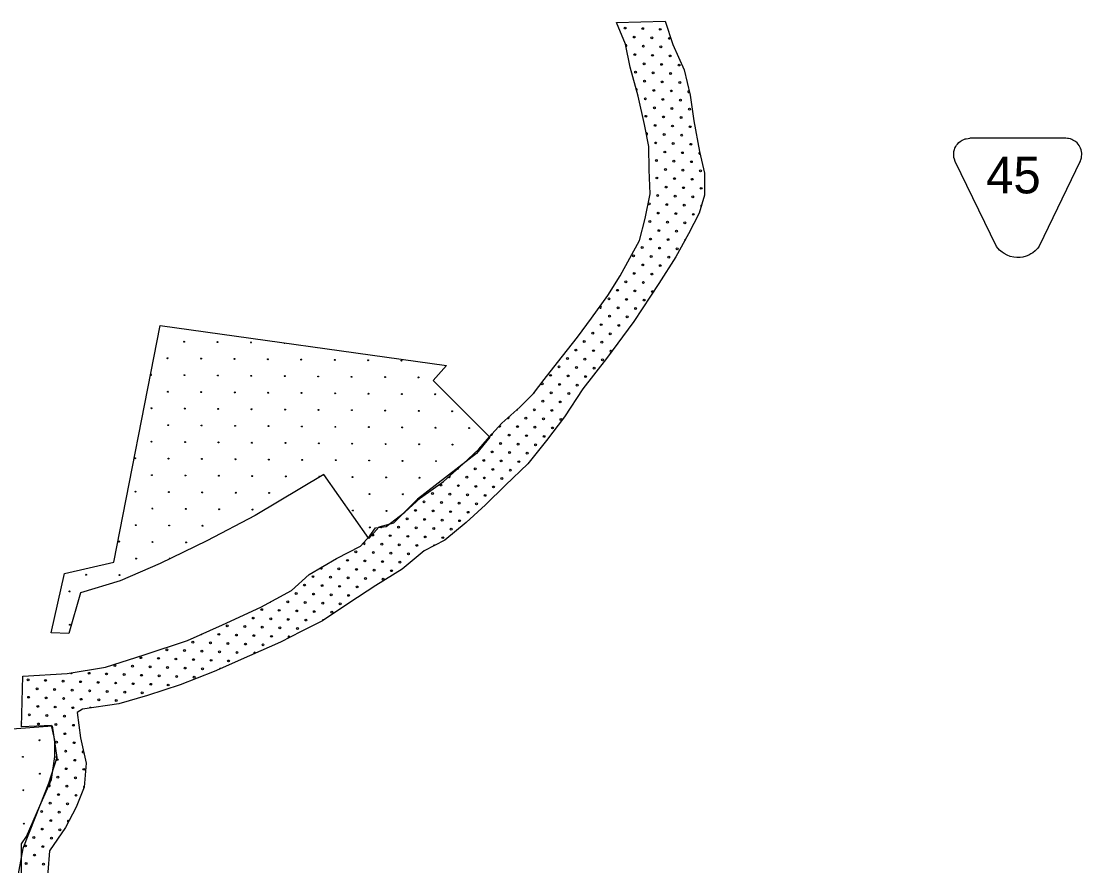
# Model space of a CAD drawing. Extents: x 1612280 to 1883141, y 560852 to 780851.
# Drawn here: x 1772365 to 1784565, y 675742 to 685456 of the extents above; entities that cross this region are included whole.
import ezdxf

# ---------------------------------------------------------------- set-up
doc = ezdxf.new("R2010")
doc.units = 0
for name, color, linetype in [('DESIGN - EROSION CONTROL - Devices', 7, 'Continuous'), ('DESIGN - ROW - Easement Linework and Patterning', 7, 'Continuous'), ('DESIGN - SCRATCH - User 1', 7, 'Continuous'), ('DESIGN - TRAFFIC CONTROL PERMANENT - Pavement Marking Text', 7, 'Continuous')]:
    doc.layers.add(name, color=color, linetype=linetype)

msp = doc.modelspace()

# ---------------------------------------------------------------- linework, layer by layer
at = {"layer": 'DESIGN - EROSION CONTROL - Devices'}
for centre in [(1774239, 681769), (1774239, 681769), (1774623, 681766), (1774623, 681766), (1775008, 681762), (1775008, 681762), (1774048, 681579), (1774048, 681579), (1774433, 681575), (1774433, 681575), (1774817, 681572), (1774817, 681572), (1775202, 681568), (1775202, 681568), (1775586, 681564), (1775586, 681564), (1775971, 681560), (1775971, 681560), (1776356, 681557), (1776356, 681557), (1776740, 681553), (1776740, 681553), (1774242, 681385), (1774242, 681385), (1774627, 681381), (1774627, 681381), (1775011, 681377), (1775011, 681377), (1775396, 681374), (1775396, 681374), (1775781, 681370), (1775781, 681370), (1776165, 681366), (1776165, 681366), (1776550, 681363), (1776550, 681363), (1776934, 681359), (1776934, 681359), (1774052, 681194), (1774052, 681194), (1774436, 681191), (1774436, 681191), (1774821, 681187), (1774821, 681187), (1775206, 681183), (1775206, 681183), (1775590, 681180), (1775590, 681180), (1775975, 681176), (1775975, 681176), (1776359, 681172), (1776359, 681172), (1776744, 681168), (1776744, 681168), (1777128, 681165), (1777128, 681165), (1773862, 681004), (1773862, 681004), (1774246, 681000), (1774246, 681000), (1774631, 680997), (1774631, 680997), (1775015, 680993), (1775015, 680993), (1775400, 680989), (1775400, 680989), (1775784, 680985), (1775784, 680985), (1776169, 680982), (1776169, 680982), (1776553, 680978), (1776553, 680978), (1776938, 680974), (1776938, 680974), (1777322, 680970), (1777322, 680970), (1774056, 680810), (1774056, 680810), (1774440, 680806), (1774440, 680806), (1774825, 680802), (1774825, 680802), (1775209, 680799), (1775209, 680799), (1775594, 680795), (1775594, 680795), (1775978, 680791), (1775978, 680791), (1776363, 680788), (1776363, 680788), (1776748, 680784), (1776748, 680784), (1777132, 680780), (1777132, 680780), (1777517, 680776), (1777517, 680776), (1773865, 680620), (1773865, 680620), (1774250, 680616), (1774250, 680616), (1774634, 680612), (1774634, 680612), (1775019, 680608), (1775019, 680608), (1775403, 680605), (1775403, 680605), (1775788, 680601), (1775788, 680601), (1776173, 680597), (1776173, 680597), (1776557, 680593), (1776557, 680593), (1776942, 680590), (1776942, 680590), (1777326, 680586), (1777326, 680586), (1773675, 680429), (1773675, 680429), (1774059, 680425), (1774059, 680425), (1774444, 680422), (1774444, 680422), (1774829, 680418), (1774829, 680418), (1775213, 680414), (1775213, 680414), (1775598, 680410), (1775598, 680410), (1775982, 680407), (1775982, 680407), (1776367, 680403), (1776367, 680403), (1776751, 680399), (1776751, 680399), (1777136, 680396), (1777136, 680396), (1773869, 680235), (1773869, 680235), (1774254, 680231), (1774254, 680231), (1774638, 680228), (1774638, 680228), (1775023, 680224), (1775023, 680224), (1775407, 680220), (1775407, 680220), (1776176, 680213), (1776176, 680213), (1776561, 680209), (1776561, 680209), (1776945, 680205), (1776945, 680205), (1773679, 680045), (1773679, 680045), (1774063, 680041), (1774063, 680041), (1774448, 680037), (1774448, 680037), (1774832, 680033), (1774832, 680033), (1775217, 680030), (1775217, 680030), (1776370, 680018), (1776370, 680018), (1776755, 680015), (1776755, 680015), (1773873, 679850), (1773873, 679850), (1774257, 679847), (1774257, 679847), (1774642, 679843), (1774642, 679843), (1775026, 679839), (1775026, 679839), (1776180, 679828), (1776180, 679828), (1776565, 679824), (1776565, 679824), (1773682, 679660), (1773682, 679660), (1774067, 679656), (1774067, 679656), (1774451, 679653), (1774451, 679653), (1776374, 679634), (1776374, 679634), (1773492, 679470), (1773492, 679470), (1773876, 679466), (1773876, 679466), (1774261, 679462), (1774261, 679462), (1773686, 679275), (1773686, 679275), (1773111, 679089), (1773111, 679089), (1773496, 679085), (1773496, 679085), (1772921, 678898), (1772921, 678898), (1772924, 678514), (1772924, 678514), (1772576, 677185), (1772576, 677185), (1772385, 676995), (1772385, 676995), (1772579, 676801), (1772579, 676801), (1772389, 676610), (1772389, 676610), (1772393, 676226), (1772393, 676226)]:
    msp.add_circle(centre, 5.28, dxfattribs=at)
for centre, start, end in [((1775392, 681758), 202.5952, 321.4914), ((1773858, 681389), 201.616, 136.1823), ((1775792, 680216), 336.6657, 265.4618), ((1774071, 679272), 10.465, 221.9957), ((1772770, 676991), 44.8233, 327.4361)]:
    msp.add_arc(centre, 5.28, start, end, dxfattribs=at)
at = {"layer": 'DESIGN - ROW - Easement Linework and Patterning'}
for points in [[(1783584, 682864), (1783109, 683844), (1783099, 683871), (1783094, 683889), (1783092, 683907), (1783091, 683923), (1783091, 683941), (1783093, 683957), (1783099, 683980), (1783106, 683998), (1783114, 684014), (1783124, 684030), (1783134, 684044), (1783149, 684060), (1783164, 684072), (1783177, 684081), (1783190, 684089), (1783206, 684096), (1783222, 684102), (1783234, 684105), (1783256, 684109), (1783275, 684110)], [(1783584, 682864), (1783109, 683844), (1783099, 683871), (1783094, 683889), (1783092, 683907), (1783091, 683923), (1783091, 683941), (1783093, 683957), (1783099, 683980), (1783106, 683998), (1783114, 684014), (1783124, 684030), (1783134, 684044), (1783149, 684060), (1783164, 684072), (1783177, 684081), (1783190, 684089), (1783206, 684096), (1783222, 684102), (1783234, 684105), (1783256, 684109), (1783275, 684110)], [(1784546, 683845), (1784552, 683862), (1784560, 683885), (1784563, 683902), (1784565, 683922), (1784564, 683938), (1784562, 683956), (1784557, 683978), (1784550, 683996), (1784544, 684011), (1784535, 684026), (1784523, 684042), (1784511, 684056), (1784492, 684072), (1784477, 684082), (1784463, 684090), (1784449, 684096), (1784433, 684102), (1784413, 684107), (1784399, 684109), (1784380, 684110), (1783275, 684110)], [(1784546, 683845), (1784552, 683862), (1784560, 683885), (1784563, 683902), (1784565, 683922), (1784564, 683938), (1784562, 683956), (1784557, 683978), (1784550, 683996), (1784544, 684011), (1784535, 684026), (1784523, 684042), (1784511, 684056), (1784492, 684072), (1784477, 684082), (1784463, 684090), (1784449, 684096), (1784433, 684102), (1784413, 684107), (1784399, 684109), (1784380, 684110), (1783275, 684110)], [(1784546, 683845), (1784073, 682867), (1784058, 682847), (1784043, 682830), (1784030, 682817), (1784002, 682794), (1783980, 682780), (1783956, 682767), (1783923, 682753), (1783886, 682743), (1783854, 682739), (1783819, 682738), (1783781, 682741), (1783741, 682750), (1783705, 682764), (1783670, 682783), (1783648, 682798), (1783618, 682823), (1783584, 682864)], [(1784546, 683845), (1784073, 682867), (1784058, 682847), (1784043, 682830), (1784030, 682817), (1784002, 682794), (1783980, 682780), (1783956, 682767), (1783923, 682753), (1783886, 682743), (1783854, 682739), (1783819, 682738), (1783781, 682741), (1783741, 682750), (1783705, 682764), (1783670, 682783), (1783648, 682798), (1783618, 682823), (1783584, 682864)]]:
    msp.add_lwpolyline(points, dxfattribs=at)
at = {"layer": 'DESIGN - SCRATCH - User 1'}
for points in [[(1779255, 682527), (1779477, 682933), (1779543, 683187), (1779599, 683472), (1779589, 683746), (1779583, 684015), (1779533, 684269), (1779462, 684593), (1779370, 684928), (1779315, 685192), (1779213, 685441), (1779771, 685456), (1779862, 685187), (1779989, 684898), (1780060, 684604), (1780101, 684309), (1780167, 683959), (1780223, 683710), (1780223, 683456), (1780162, 683248), (1780040, 683010), (1779893, 682746), (1779700, 682438)], [(1779255, 682527), (1779477, 682933), (1779543, 683187), (1779599, 683472), (1779589, 683746), (1779583, 684015), (1779533, 684269), (1779462, 684593), (1779370, 684928), (1779315, 685192), (1779213, 685441), (1779771, 685456), (1779862, 685187), (1779989, 684898), (1780060, 684604), (1780101, 684309), (1780167, 683959), (1780223, 683710), (1780223, 683456), (1780162, 683248), (1780040, 683010), (1779893, 682746), (1779700, 682438)], [(1776439, 679630), (1776561, 679643), (1776776, 679811), (1776959, 679973), (1777221, 680162), (1777447, 680367), (1777630, 680534), (1777777, 680707), (1777892, 680833), (1778102, 681017), (1778259, 681174), (1778380, 681337), (1778532, 681531), (1778762, 681824), (1778925, 682039), (1779113, 682302), (1779255, 682527)], [(1776439, 679630), (1776561, 679643), (1776776, 679811), (1776959, 679973), (1777221, 680162), (1777447, 680367), (1777630, 680534), (1777777, 680707), (1777892, 680833), (1778102, 681017), (1778259, 681174), (1778380, 681337), (1778532, 681531), (1778762, 681824), (1778925, 682039), (1779113, 682302), (1779255, 682527)], [(1779700, 682438), (1779412, 682003), (1779098, 681578), (1778825, 681227), (1778615, 680907), (1778406, 680634), (1778191, 680367), (1777934, 680120), (1777704, 679895), (1777484, 679690), (1777237, 679486), (1777001, 679365), (1776745, 679152)], [(1779700, 682438), (1779412, 682003), (1779098, 681578), (1778825, 681227), (1778615, 680907), (1778406, 680634), (1778191, 680367), (1777934, 680120), (1777704, 679895), (1777484, 679690), (1777237, 679486), (1777001, 679365), (1776745, 679152)], [(1773431, 679234), (1773964, 681955)], [(1773431, 679234), (1773964, 681955)], [(1773964, 681955), (1777258, 681495), (1777102, 681322), (1777754, 680670)], [(1773964, 681955), (1777258, 681495), (1777102, 681322), (1777754, 680670)], [(1777754, 680670), (1777603, 680484), (1776922, 679957), (1776648, 679683), (1776478, 679637), (1776363, 679506), (1775844, 680243)], [(1777754, 680670), (1777603, 680484), (1776922, 679957), (1776648, 679683), (1776478, 679637), (1776363, 679506), (1775844, 680243)], [(1775844, 680243), (1775057, 679769), (1774498, 679481), (1773964, 679218), (1773504, 679021), (1773045, 678881), (1772913, 678412), (1772708, 678420), (1772864, 679103), (1773431, 679234)], [(1775844, 680243), (1775057, 679769), (1774498, 679481), (1773964, 679218), (1773504, 679021), (1773045, 678881), (1772913, 678412), (1772708, 678420), (1772864, 679103), (1773431, 679234)], [(1772383, 677921), (1772892, 677954), (1773335, 678028), (1773778, 678167), (1774276, 678333), (1774682, 678513), (1775120, 678716), (1775475, 678910), (1775678, 679094), (1775992, 679275), (1776269, 679418), (1776375, 679538), (1776439, 679630)], [(1772383, 677921), (1772892, 677954), (1773335, 678028), (1773778, 678167), (1774276, 678333), (1774682, 678513), (1775120, 678716), (1775475, 678910), (1775678, 679094), (1775992, 679275), (1776269, 679418), (1776375, 679538), (1776439, 679630)], [(1776745, 679152), (1776443, 678966), (1776133, 678761), (1775831, 678561), (1775586, 678437), (1775347, 678312), (1774991, 678157), (1774583, 677975), (1774192, 677824), (1773819, 677699), (1773486, 677606), (1773069, 677544), (1773009, 677505)], [(1776745, 679152), (1776443, 678966), (1776133, 678761), (1775831, 678561), (1775586, 678437), (1775347, 678312), (1774991, 678157), (1774583, 677975), (1774192, 677824), (1773819, 677699), (1773486, 677606), (1773069, 677544), (1773009, 677505)], [(1770477, 678586), (1770638, 678446), (1770828, 678182), (1770981, 677870), (1771150, 677653), (1771388, 677484), (1771642, 677383), (1771943, 677341), (1772207, 677314), (1772720, 677351)], [(1770477, 678586), (1770638, 678446), (1770828, 678182), (1770981, 677870), (1771150, 677653), (1771388, 677484), (1771642, 677383), (1771943, 677341), (1772207, 677314), (1772720, 677351)], [(1773009, 677505), (1773047, 677213), (1773112, 676922), (1773090, 676646), (1772998, 676414), (1772874, 676182), (1772691, 675912), (1772669, 675669), (1772658, 675432), (1772647, 675189), (1772583, 674924), (1772480, 674622), (1772432, 674352), (1772372, 674362), (1772367, 675993), (1772426, 676080), (1772577, 676431), (1772712, 676733), (1772750, 676997), (1772750, 677186), (1772712, 677354), (1772367, 677338), (1772383, 677921)], [(1773009, 677505), (1773047, 677213), (1773112, 676922), (1773090, 676646), (1772998, 676414), (1772874, 676182), (1772691, 675912), (1772669, 675669), (1772658, 675432), (1772647, 675189), (1772583, 674924), (1772480, 674622), (1772432, 674352), (1772372, 674362), (1772367, 675993), (1772426, 676080), (1772577, 676431), (1772712, 676733), (1772750, 676997), (1772750, 677186), (1772712, 677354), (1772367, 677338), (1772383, 677921)], [(1772720, 677351), (1772774, 676989), (1772679, 676688), (1772521, 676291), (1772383, 675942), (1772320, 675588), (1772352, 675186), (1772315, 674784), (1772204, 674387), (1772093, 674086), (1771908, 673668), (1771776, 673330)], [(1772720, 677351), (1772774, 676989), (1772679, 676688), (1772521, 676291), (1772383, 675942), (1772320, 675588), (1772352, 675186), (1772315, 674784), (1772204, 674387), (1772093, 674086), (1771908, 673668), (1771776, 673330)]]:
    msp.add_lwpolyline(points, dxfattribs=at)
for centre in [(1778372, 680883), (1778372, 680883), (1778274, 680786), (1778274, 680786), (1778476, 680778), (1778476, 680778), (1778379, 680681), (1778379, 680681), (1778282, 680584), (1778282, 680584)]:
    msp.add_circle(centre, 10.6, dxfattribs=at)
at = {"layer": 'DESIGN - TRAFFIC CONTROL PERMANENT - Pavement Marking Text'}
for centre in [(1779312, 685378), (1779312, 685378), (1779417, 685274), (1779417, 685274), (1779514, 685371), (1779514, 685371), (1779619, 685266), (1779619, 685266), (1779716, 685363), (1779716, 685363), (1779521, 685169), (1779521, 685169), (1779723, 685162), (1779723, 685162), (1779820, 685259), (1779820, 685259), (1779424, 685072), (1779424, 685072), (1779626, 685064), (1779626, 685064), (1779828, 685057), (1779828, 685057), (1779529, 684967), (1779529, 684967), (1779731, 684960), (1779731, 684960), (1779932, 684952), (1779932, 684952), (1779432, 684870), (1779432, 684870), (1779633, 684863), (1779633, 684863), (1779835, 684855), (1779835, 684855), (1779536, 684766), (1779536, 684766), (1779641, 684661), (1779641, 684661), (1779738, 684758), (1779738, 684758), (1779843, 684654), (1779843, 684654), (1779940, 684751), (1779940, 684751), (1779544, 684564), (1779544, 684564), (1779745, 684557), (1779745, 684557), (1779947, 684549), (1779947, 684549), (1779648, 684460), (1779648, 684460), (1779850, 684452), (1779850, 684452), (1780052, 684445), (1780052, 684445), (1779551, 684363), (1779551, 684363), (1779753, 684355), (1779753, 684355), (1779955, 684348), (1779955, 684348), (1779656, 684258), (1779656, 684258), (1779857, 684251), (1779857, 684251), (1780059, 684243), (1780059, 684243), (1779663, 684056), (1779663, 684056), (1779760, 684153), (1779760, 684153), (1779865, 684049), (1779865, 684049), (1779962, 684146), (1779962, 684146), (1780067, 684041), (1780067, 684041), (1779768, 683952), (1779768, 683952), (1779970, 683944), (1779970, 683944), (1779671, 683855), (1779671, 683855), (1779872, 683847), (1779872, 683847), (1780074, 683840), (1780074, 683840), (1779775, 683750), (1779775, 683750), (1779977, 683743), (1779977, 683743), (1780179, 683735), (1780179, 683735), (1779678, 683653), (1779678, 683653), (1779880, 683646), (1779880, 683646), (1780082, 683638), (1780082, 683638), (1779686, 683452), (1779686, 683452), (1779783, 683549), (1779783, 683549), (1779887, 683444), (1779887, 683444), (1779984, 683541), (1779984, 683541), (1780089, 683437), (1780089, 683437), (1780186, 683534), (1780186, 683534), (1779589, 683355), (1779589, 683355), (1779790, 683347), (1779790, 683347), (1779992, 683340), (1779992, 683340), (1779693, 683250), (1779693, 683250), (1779895, 683243), (1779895, 683243), (1780096, 683235), (1780096, 683235), (1779596, 683153), (1779596, 683153), (1779798, 683145), (1779798, 683145), (1779999, 683138), (1779999, 683138), (1779604, 682951), (1779604, 682951), (1779701, 683048), (1779701, 683048), (1779805, 682944), (1779805, 682944), (1779902, 683041), (1779902, 683041), (1779507, 682854), (1779507, 682854), (1779708, 682847), (1779708, 682847), (1779910, 682839), (1779910, 682839), (1779409, 682757), (1779409, 682757), (1779611, 682750), (1779611, 682750), (1779813, 682742), (1779813, 682742), (1779514, 682653), (1779514, 682653), (1779716, 682645), (1779716, 682645), (1779320, 682458), (1779320, 682458), (1779417, 682556), (1779417, 682556), (1779619, 682548), (1779619, 682548), (1779223, 682361), (1779223, 682361), (1779424, 682354), (1779424, 682354), (1779521, 682451), (1779521, 682451), (1779626, 682346), (1779626, 682346), (1779126, 682264), (1779126, 682264), (1779327, 682257), (1779327, 682257), (1779529, 682249), (1779529, 682249), (1779230, 682160), (1779230, 682160), (1779432, 682152), (1779432, 682152), (1779133, 682063), (1779133, 682063), (1779335, 682055), (1779335, 682055), (1778939, 681869), (1778939, 681869), (1779036, 681966), (1779036, 681966), (1779141, 681861), (1779141, 681861), (1779238, 681958), (1779238, 681958), (1778842, 681772), (1778842, 681772), (1779044, 681764), (1779044, 681764), (1778745, 681674), (1778745, 681674), (1778947, 681667), (1778947, 681667), (1778551, 681480), (1778551, 681480), (1778648, 681577), (1778648, 681577), (1778849, 681570), (1778849, 681570), (1779051, 681562), (1779051, 681562), (1778454, 681383), (1778454, 681383), (1778655, 681376), (1778655, 681376), (1778752, 681473), (1778752, 681473), (1778857, 681368), (1778857, 681368), (1778954, 681465), (1778954, 681465), (1778357, 681286), (1778357, 681286), (1778558, 681279), (1778558, 681279), (1778760, 681271), (1778760, 681271), (1778461, 681182), (1778461, 681182), (1778663, 681174), (1778663, 681174), (1778364, 681085), (1778364, 681085), (1778566, 681077), (1778566, 681077), (1778170, 680890), (1778170, 680890), (1778267, 680987), (1778267, 680987), (1778469, 680980), (1778469, 680980), (1778573, 680875), (1778573, 680875), (1778073, 680793), (1778073, 680793), (1777976, 680696), (1777976, 680696), (1778177, 680689), (1778177, 680689), (1777879, 680599), (1777879, 680599), (1778080, 680592), (1778080, 680592), (1777685, 680405), (1777685, 680405), (1777782, 680502), (1777782, 680502), (1777886, 680398), (1777886, 680398), (1777983, 680495), (1777983, 680495), (1778088, 680390), (1778088, 680390), (1778185, 680487), (1778185, 680487), (1777588, 680308), (1777588, 680308), (1777789, 680301), (1777789, 680301), (1777991, 680293), (1777991, 680293), (1777490, 680211), (1777490, 680211), (1777692, 680203), (1777692, 680203), (1777894, 680196), (1777894, 680196), (1777095, 680024), (1777095, 680024), (1777192, 680121), (1777192, 680121), (1777296, 680017), (1777296, 680017), (1777393, 680114), (1777393, 680114), (1777595, 680106), (1777595, 680106), (1777797, 680099), (1777797, 680099), (1776998, 679927), (1776998, 679927), (1777199, 679920), (1777199, 679920), (1777401, 679912), (1777401, 679912), (1777498, 680009), (1777498, 680009), (1777602, 679905), (1777602, 679905), (1777700, 680002), (1777700, 680002), (1776901, 679830), (1776901, 679830), (1777102, 679823), (1777102, 679823), (1777304, 679815), (1777304, 679815), (1777505, 679808), (1777505, 679808), (1776803, 679733), (1776803, 679733), (1777005, 679726), (1777005, 679726), (1777207, 679718), (1777207, 679718), (1777408, 679711), (1777408, 679711), (1776408, 679546), (1776408, 679546), (1776609, 679539), (1776609, 679539), (1776706, 679636), (1776706, 679636), (1776811, 679531), (1776811, 679531), (1776908, 679628), (1776908, 679628), (1777110, 679621), (1777110, 679621), (1777311, 679614), (1777311, 679614), (1776512, 679442), (1776512, 679442), (1776714, 679434), (1776714, 679434), (1776915, 679427), (1776915, 679427), (1777013, 679524), (1777013, 679524), (1777214, 679516), (1777214, 679516), (1776214, 679352), (1776214, 679352), (1776415, 679345), (1776415, 679345), (1776617, 679337), (1776617, 679337), (1776818, 679330), (1776818, 679330), (1776117, 679255), (1776117, 679255), (1776318, 679248), (1776318, 679248), (1776520, 679240), (1776520, 679240), (1776721, 679233), (1776721, 679233), (1775721, 679068), (1775721, 679068), (1775922, 679061), (1775922, 679061), (1776019, 679158), (1776019, 679158), (1776124, 679054), (1776124, 679054), (1776221, 679151), (1776221, 679151), (1776326, 679046), (1776326, 679046), (1776423, 679143), (1776423, 679143), (1776624, 679136), (1776624, 679136), (1775624, 678971), (1775624, 678971), (1775825, 678964), (1775825, 678964), (1776027, 678956), (1776027, 678956), (1776229, 678949), (1776229, 678949), (1776527, 679039), (1776527, 679039), (1775527, 678874), (1775527, 678874), (1775728, 678867), (1775728, 678867), (1775930, 678859), (1775930, 678859), (1776131, 678852), (1776131, 678852), (1775131, 678688), (1775131, 678688), (1775332, 678680), (1775332, 678680), (1775430, 678777), (1775430, 678777), (1775631, 678770), (1775631, 678770), (1775833, 678762), (1775833, 678762), (1776034, 678755), (1776034, 678755), (1775034, 678591), (1775034, 678591), (1775235, 678583), (1775235, 678583), (1775437, 678576), (1775437, 678576), (1775534, 678673), (1775534, 678673), (1775639, 678568), (1775639, 678568), (1775736, 678665), (1775736, 678665), (1775937, 678658), (1775937, 678658), (1774735, 678501), (1774735, 678501), (1774937, 678493), (1774937, 678493), (1775138, 678486), (1775138, 678486), (1775340, 678479), (1775340, 678479), (1775542, 678471), (1775542, 678471), (1774339, 678314), (1774339, 678314), (1774638, 678404), (1774638, 678404), (1774840, 678396), (1774840, 678396), (1775041, 678389), (1775041, 678389), (1775243, 678381), (1775243, 678381), (1774041, 678225), (1774041, 678225), (1774242, 678217), (1774242, 678217), (1774444, 678210), (1774444, 678210), (1774541, 678307), (1774541, 678307), (1774645, 678202), (1774645, 678202), (1774743, 678299), (1774743, 678299), (1774847, 678195), (1774847, 678195), (1774944, 678292), (1774944, 678292), (1775146, 678284), (1775146, 678284), (1773742, 678135), (1773742, 678135), (1773944, 678128), (1773944, 678128), (1774145, 678120), (1774145, 678120), (1774347, 678113), (1774347, 678113), (1774548, 678105), (1774548, 678105), (1774750, 678098), (1774750, 678098), (1773145, 677956), (1773145, 677956), (1773346, 677948), (1773346, 677948), (1773443, 678045), (1773443, 678045), (1773645, 678038), (1773645, 678038), (1773847, 678031), (1773847, 678031), (1774048, 678023), (1774048, 678023), (1774250, 678016), (1774250, 678016), (1774451, 678008), (1774451, 678008), (1772443, 677881), (1772443, 677881), (1772644, 677874), (1772644, 677874), (1772846, 677866), (1772846, 677866), (1773048, 677859), (1773048, 677859), (1773249, 677851), (1773249, 677851), (1773451, 677844), (1773451, 677844), (1773548, 677941), (1773548, 677941), (1773652, 677836), (1773652, 677836), (1773749, 677933), (1773749, 677933), (1773854, 677829), (1773854, 677829), (1773951, 677926), (1773951, 677926), (1774056, 677821), (1774056, 677821), (1774153, 677919), (1774153, 677919), (1774354, 677911), (1774354, 677911), (1772547, 677777), (1772547, 677777), (1772749, 677769), (1772749, 677769), (1772950, 677762), (1772950, 677762), (1773152, 677754), (1773152, 677754), (1773354, 677747), (1773354, 677747), (1773555, 677739), (1773555, 677739), (1773757, 677732), (1773757, 677732), (1772450, 677680), (1772450, 677680), (1772555, 677575), (1772555, 677575), (1772652, 677672), (1772652, 677672), (1772853, 677665), (1772853, 677665), (1773055, 677657), (1773055, 677657), (1773257, 677650), (1773257, 677650), (1773458, 677642), (1773458, 677642), (1772458, 677478), (1772458, 677478), (1772659, 677470), (1772659, 677470), (1772756, 677568), (1772756, 677568), (1772861, 677463), (1772861, 677463), (1772958, 677560), (1772958, 677560), (1772562, 677373), (1772562, 677373), (1772764, 677366), (1772764, 677366), (1772965, 677358), (1772965, 677358), (1772868, 677261), (1772868, 677261), (1772771, 677164), (1772771, 677164), (1772973, 677157), (1772973, 677157), (1772876, 677060), (1772876, 677060), (1772779, 676963), (1772779, 676963), (1772883, 676858), (1772883, 676858), (1772980, 676955), (1772980, 676955), (1773085, 676851), (1773085, 676851), (1772786, 676761), (1772786, 676761), (1772988, 676754), (1772988, 676754), (1772891, 676657), (1772891, 676657), (1772794, 676560), (1772794, 676560), (1772995, 676552), (1772995, 676552), (1772600, 676365), (1772600, 676365), (1772697, 676462), (1772697, 676462), (1772801, 676358), (1772801, 676358), (1772898, 676455), (1772898, 676455), (1772704, 676261), (1772704, 676261), (1772607, 676164), (1772607, 676164), (1772809, 676156), (1772809, 676156), (1772510, 676067), (1772510, 676067), (1772712, 676059), (1772712, 676059), (1772413, 675970), (1772413, 675970), (1772614, 675962), (1772614, 675962), (1772420, 675768), (1772420, 675768), (1772517, 675865), (1772517, 675865), (1772622, 675761), (1772622, 675761)]:
    msp.add_circle(centre, 10.6, dxfattribs=at)
for centre, start, end in [((1779320, 685176), 271.7278, 112.1458), ((1779439, 684669), 294.9034, 95.5867), ((1780044, 684646), 70.8982, 316.2257), ((1779559, 684161), 256.0676, 126.5374), ((1780171, 683937), 99.014, 286.276), ((1780194, 683332), 114.171, 213.2199), ((1779499, 683056), 317.7134, 13.1577), ((1780007, 682936), 99.634, 202.1026), ((1779029, 682167), 167.2465, 121.2787), ((1779148, 681660), 4.8322, 282.1444), ((1778260, 681189), 287.5376, 359.3525), ((1778162, 681092), 302.3402, 327.6962), ((1777968, 680898), 212.9889, 49.4202), ((1778065, 680995), 267.0634, 355.3458), ((1778670, 680973), 123.8558, 169.6691), ((1777871, 680801), 189.8766, 85.1363), ((1777774, 680704), 228.2579, 49.9162), ((1777483, 680413), 286.4576, 338.4508), ((1777386, 680315), 239.165, 25.2862), ((1777289, 680218), 202.4777, 61.9735), ((1776505, 679643), 223.7057, 328.4393), ((1776311, 679449), 145.6373, 131.4048), ((1777117, 679419), 50.8407, 183.3351), ((1775818, 679166), 161.4938, 78.2094), ((1775228, 678785), 263.4228, 333.8282), ((1775840, 678561), 66.155, 180.0558), ((1774436, 678411), 243.0833, 344.7496), ((1775444, 678374), 321.0567, 273.7877), ((1775049, 678187), 355.6718, 231.6143), ((1772943, 677963), 192.1782, 6.7585), ((1774653, 678001), 51.0699, 176.9977), ((1773160, 677553), 33.8757, 163.0785), ((1772361, 677381), 313.42, 43.3993), ((1773077, 677052), 74.1545, 310.8856), ((1772689, 676664), 204.6602, 107.2528), ((1773092, 676649), 97.5231, 241.5028), ((1772502, 676268), 272.5954, 40.8203), ((1772906, 676253), 28.9772, 274.7707)]:
    msp.add_arc(centre, 10.6, start, end, dxfattribs=at)

# ---------------------------------------------------------------- texts
at = {"layer": 'DESIGN - ROW - Easement Linework and Patterning'}
msp.add_text('45', height=422.4, rotation=0.0012, dxfattribs=at).set_placement((1783464, 683476))
msp.add_text('45', height=422.4, rotation=0.0012, dxfattribs=at).set_placement((1783464, 683476))

doc.saveas('drawing.dxf')
